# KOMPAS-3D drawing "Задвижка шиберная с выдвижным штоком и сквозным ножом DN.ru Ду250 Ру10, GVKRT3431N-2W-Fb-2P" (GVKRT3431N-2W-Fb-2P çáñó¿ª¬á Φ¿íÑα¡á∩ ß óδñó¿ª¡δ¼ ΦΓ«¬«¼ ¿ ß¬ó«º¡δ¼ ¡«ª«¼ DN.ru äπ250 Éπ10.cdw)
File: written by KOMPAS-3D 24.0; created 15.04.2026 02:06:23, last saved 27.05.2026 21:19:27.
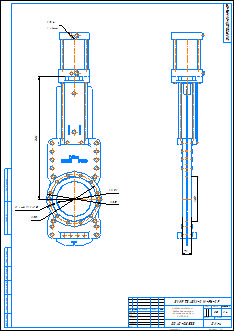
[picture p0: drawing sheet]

Document properties: Автор: DN.ru; Форматы листов документа: A2; Полное имя файла: GVKRT3431N-2W-Fb-2P Задвижка шиберная с выдвижным штоком и сквозным ножом DN.ru Ду250 Ру10.m3d; Масса: 86; Наименование: Задвижка шиберная с выдвижным штоком и сквозным ножом DN.ru Ду250 Ру10; Количество листов документа: 1; Примечание: D040-08533

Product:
- Part/product: Задвижка шиберная с выдвижным штоком и сквозным ножом DN.ru Ду250 Ру10  | designation GVKRT3431N-2W-Fb-2P
    Масса: 86
    Раздел спецификации: Прочие изделия
    Примечание: D040-08533

Views: Вид 1, Вид:1, Проекционный вид 2
Referenced files in C:\Работа\GVKRT3431N-2W-Fb-2P Задвижка шиберная со сквозным ножом DN.ru Ду100-250 Ру16\DN100\: GVKRT3431N-2W-Fb-2P Задвижка шиберная со сквозным ножом DN.ru Ду100 Ру16.m3d
Referenced files in C:\Работа\ГОТОВЫЕ ИСХОДНИКИ\GVKRT3431N-2W-Fb-2P Задвижка шиберная со сквозным ножом DN.ru Ду100-250 Ру16\DN250\: GVKRT3431N-2W-Fb-2P Задвижка шиберная с выдвижным штоком и сквозным ножом DN.ru Ду250 Ру10.m3d
Referenced files in C:\Program Files\ASCON\KOMPAS-3D v24\Templates\: Чертеж_DN.ru.cdt
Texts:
  GVKRT3431N-2W-Fb-2P
  Чертеж_DN.ru.cdt
  Задвижка шиберная с
  выдвижным штоком и
  сквозным ножом DN.ru
  Ду250 Ру10
  Задвижка шиберная с выдвижным штоком и сквозным ножом DN.ru Ду250 Ру10
  GVKRT3431N-2W-Fb-2P Задвижка шиберная с выдвижным штоком и сквозным ножом DN.ru Ду250 Ру10
Dimensions and other numbers on the sheet: 0; 3; 2; 4; 880; 350; 395; 250; 2 места; 12 отв.; 20; 70; 319; 1:4; 1; 86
